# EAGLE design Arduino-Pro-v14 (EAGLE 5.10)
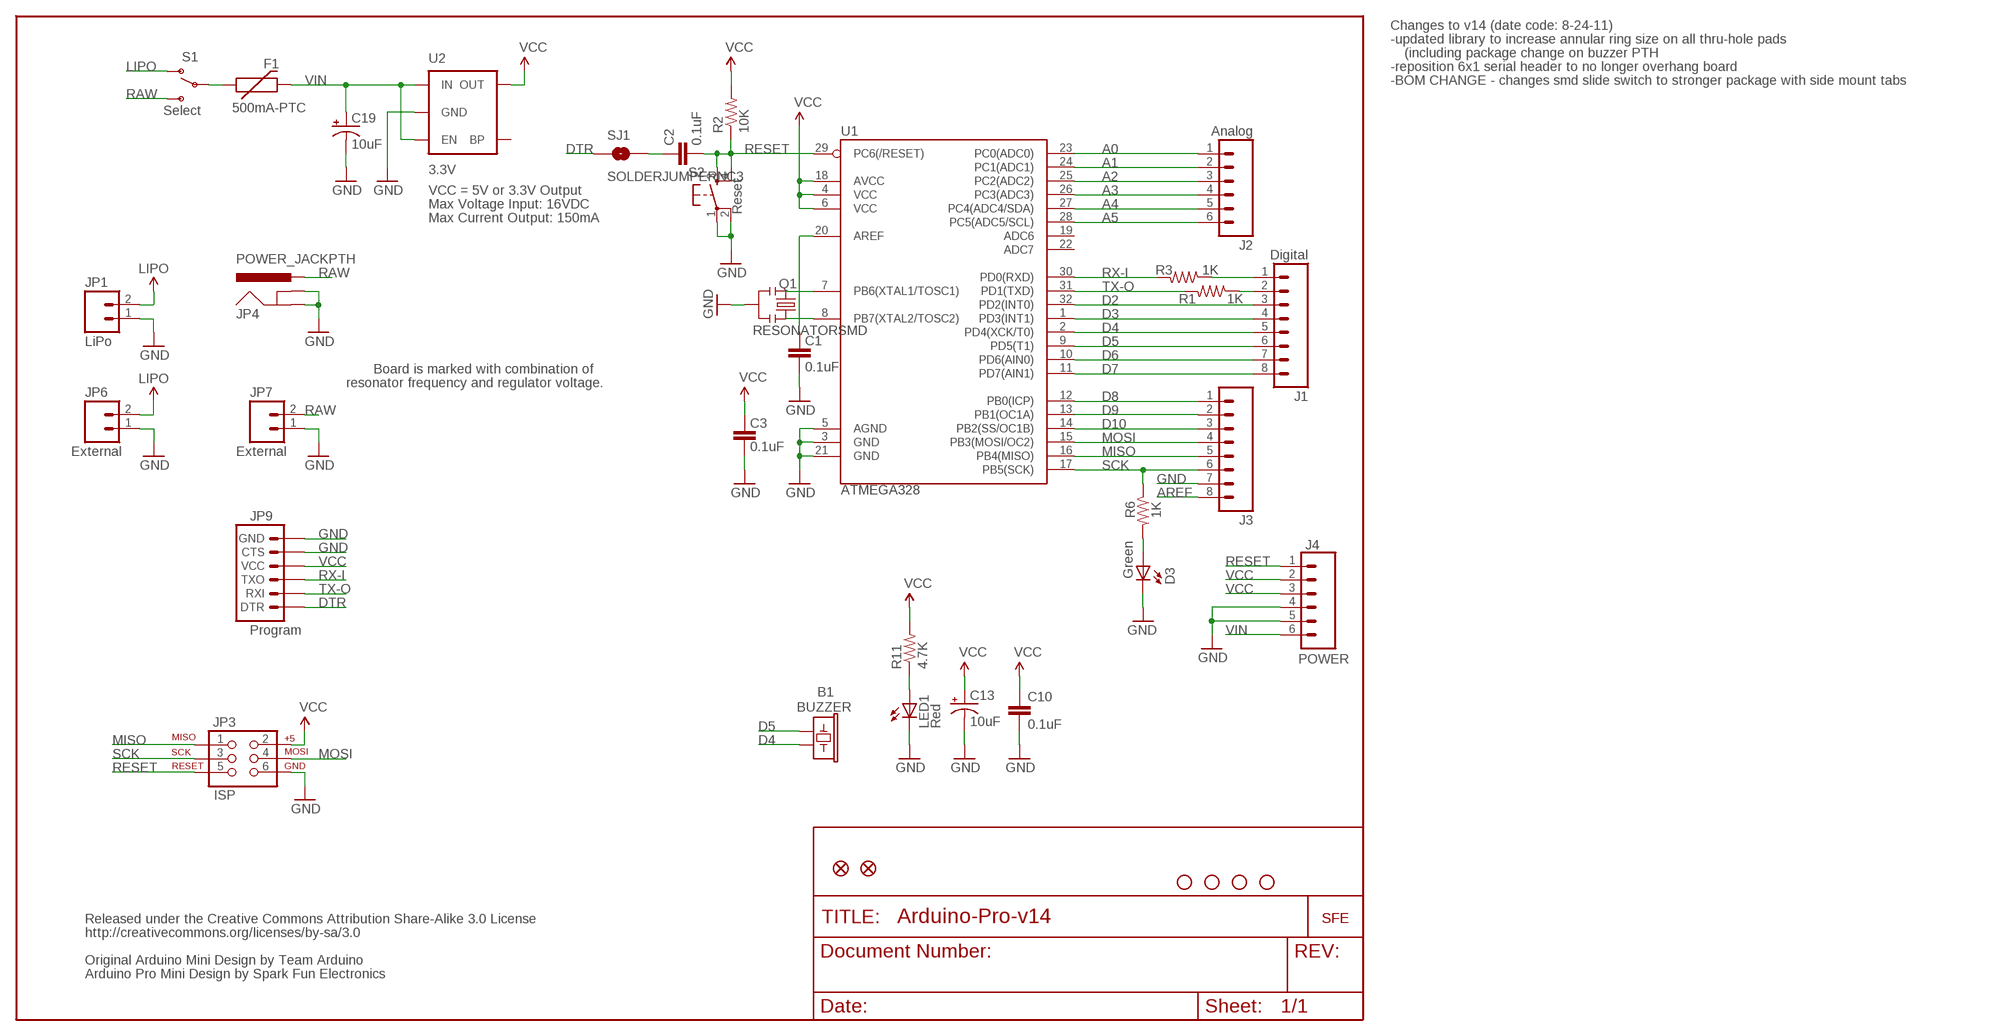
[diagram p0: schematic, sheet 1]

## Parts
B1  BUZZER  BUZZERPTH  [BUZZER-12MM]
C1  0.1uF  CAP0402-CAP  [0402-CAP]
C2  0.1uF  CAP0402-CAP  [0402-CAP]
C3  0.1uF  CAP0402-CAP  [0402-CAP]
C10  0.1uF  CAP0402-CAP  [0402-CAP]
C13  10uF  CAP_POL1206  [EIA3216]
C19  10uF  CAP_POL1206  [EIA3216]
D3  Green  LED0603  [LED-0603]
F1  500mA-PTC  PTCSMD  [PTC-1206]
J1  Digital  M081X08  [1X08]
J2  Analog  M06SIP  [1X06]
J3  M081X08  [1X08]
J4  POWER  M06SIP  [1X06]
JP1  LiPo  M02-JST-2MM-SMT  [JST-2-SMD]
JP2  FIDUCIAL1X2.5  [FIDUCIAL-1X2.5]
JP3  ISP  AVR_SPI_PRG_6PTH  [2X3]
JP4  POWER_JACKPTH  [POWER_JACK_PTH]
JP5  FIDUCIAL1X2.5  [FIDUCIAL-1X2.5]
JP6  External  M02PTH  [1X02]
JP7  External  M02PTH  [1X02]
JP9  Program  ARDUINO_SERIAL_PROGRAMSMD  [1X06-SMD]
LED1  Red  LED0603  [LED-0603]
Q1  RESONATORSMD  [RESONATOR-SMD]
R1  1K  RESISTOR0402-RES  [0402-RES]
R2  10K  RESISTOR0402-RES  [0402-RES]
R3  1K  RESISTOR0402-RES  [0402-RES]
R6  1K  RESISTOR0402-RES  [0402-RES]
R11  4.7K  RESISTOR0402-RES  [0402-RES]
S1  Select  SWITCH-SPST-SMD-A  [SWITCH-SPST-SMD-A]
S2  Reset  TAC_SWITCHSMD  [TACTILE_SWITCH_SMD]
SJ1  SOLDERJUMPERNC3  SOLDERJUMPERNC2  [SJ_2S-NOTRACE]
U1  ATMEGA328  ATMEGA168  [TQFP32-08]
U2  3.3V  V_REG_LDOSMD  [SOT23-5]
U$1  STAND-OFF  [STAND-OFF]
U$3  STAND-OFF  [STAND-OFF]
U$9  STAND-OFF  [STAND-OFF]
U$10  STAND-OFF  [STAND-OFF]
U$11  LOGO-SFENEW  [SFE-NEW-WEBLOGO]

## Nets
A0: J2.1 U1.23(PC0(ADC0))
A1: J2.2 U1.24(PC1(ADC1))
A2: J2.3 U1.25(PC2(ADC2))
A3: J2.4 U1.26(PC3(ADC3))
A4: J2.5 U1.27(PC4(ADC4/SDA))
A5: J2.6 U1.28(PC5(ADC5/SCL))
AREF: C1.2 J3.8 U1.20(AREF)
D2: J1.3 U1.32(PD2(INT0))
D3: J1.4 U1.1(PD3(INT1))
D4: B1.- J1.5 U1.2(PD4(XCK/T0))
D5: B1.+ J1.6 U1.9(PD5(T1))
D6: J1.7 U1.10(PD6(AIN0))
D7: J1.8 U1.11(PD7(AIN1))
D8: J3.1 U1.12(PB0(ICP))
D9: J3.2 U1.13(PB1(OC1A))
D10: J3.3 U1.14(PB2(SS/OC1B))
DTR: JP9.1(DTR) SJ1.1
GND [vcc]: C1.1 C3.1 C10.2 C13.C(-) C19.C(-) D3.C J3.7 J4.4 J4.5 JP1.1 JP3.6 JP4.GND JP4.GNDBREAK JP6.1 JP7.1 JP9.5(CTS) JP9.6(GND) LED1.C Q1.2 S2.1 S2.2 U1.3(GND) U1.5(AGND) U1.21(GND) U2.2(GND)
LIPO: JP1.2 JP6.2 S1.1(O)
MISO: J3.5 JP3.1 U1.16(PB4(MISO))
MOSI: J3.4 JP3.4 U1.15(PB3(MOSI/OC2))
N$1: C2.1 SJ1.2
N$3: Q1.1 U1.8(PB7(XTAL2/TOSC2))
N$4: Q1.3 U1.7(PB6(XTAL1/TOSC1))
N$7: D3.A R6.2
N$25: F1.1 S1.2(P)
N$38: LED1.A R11.1
RAW [vcc]: JP4.PWR JP7.2 S1.3(S)
RESET: C2.2 J4.1 JP3.5 R2.1 S2.3 S2.4 U1.29(PC6(/RESET))
RX-I: JP9.3(TXO) R3.2 U1.30(PD0(RXD))
RX-IP: J1.2 R1.1
SCK: J3.6 JP3.3 R6.1 U1.17(PB5(SCK))
TX-O: JP9.2(RXI) R1.2 U1.31(PD1(TXD))
TX-OP: J1.1 R3.1
VCC: C3.2 C10.1 C13.A(+) J4.2 J4.3 JP3.2 JP9.4(VCC) R2.2 R11.2 U1.4(VCC) U1.6(VCC) U1.18(AVCC) U2.5(OUT)
VIN [vcc]: C19.A(+) F1.2 J4.6 U2.1(IN) U2.3(EN)
Unconnected: U1.19(ADC6) U1.22(ADC7) U2.4(BP)

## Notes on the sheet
- Changes to v14 (date code: 8-24-11)
- -updated library to increase annular ring size on all thru-hole pads
- (including package change on buzzer PTH
- -reposition 6x1 serial header to no longer overhang board
- -BOM CHANGE - changes smd slide switch to stronger package with side mount tabs
- VCC = 5V or 3.3V Output
- Max Voltage Input: 16VDC
- Max Current Output: 150mA
- Board is marked with combination of
- resonator frequency and regulator voltage.
- Released under the Creative Commons Attribution Share-Alike 3.0 License
- http://creativecommons.org/licenses/by-sa/3.0
- Original Arduino Mini Design by Team Arduino
- Arduino Pro Mini Design by Spark Fun Electronics

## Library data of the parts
B1 = SparkFun:BUZZER: Buzzer 12mm
C1-C3 C10 = SparkFun:CAP: Capacitor
C13 C19 = SparkFun:CAP_POL: Capacitor Polarized
D3 LED1 = SparkFun:LED: LEDs
F1 = SparkFun:PTC: Resettable Fuse PTC
J1 J3 = SparkFun:M08: Header 8 Standard 8-pin 0.1" header. Use with straight break away headers (SKU : PRT-00116), right angle break away headers (PRT-00553), swiss pins (PRT-00743), machine pins (PRT-00117), and female headers (PRT-00115).
J2 J4 = SparkFun:M06: Header 6 Standard 6-pin 0.1" header. Use with straight break away headers (SKU : PRT-00116), right angle break away headers (PRT-00553), swiss pins (PRT-00743), machine pins (PRT-00117), and female headers (PRT-00115). Molex polarized connector foot print use with SKU : PRT-08094 with associated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
JP1 JP6 JP7 = SparkFun:M02: Header 2
JP2 JP5 = abes:FIDUCIAL: Fiducial Alignment Points
JP3 = SparkFun:AVR_SPI_PRG_6: AVR ISP 6 Pin This is the reduced ISP connector for AVR programming. Common on Arduino. This footprint will take up less PCB space and can be used with a 10-pin to 6-pin adapter such as SKU: BOB-08508
JP4 = SparkFun:POWER_JACK: Power Jack This is the standard 5.5mm barrel jack for power. The PTH is the most common, proven, reliable, footprint. All others are experimental. The Slot footprint only works if the mill layer is transmitted to the PCB fab house so be warned. Spark Fun Electronics SKU : PRT-00119. Mating wall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
JP9 = SparkFun:ARDUINO_SERIAL_PROGRAM
Q1 = SparkFun:RESONATOR: Resonator Small SMD resonator. This is the itty bitty 10/20MHz resonators with built in caps. CSTCE10M0G55 and CSTCE20M0V53. Footprint has been reviewed closely but hasn't been tested yet.
R1-R3 R6 R11 = SparkFun:RESISTOR: Resistor
S1 = SparkFun:SWITCH-SPST: SPST Switch Simple slide switch. Spark Fun Electronics SKU : COM-00102
S2 = SparkFun:TAC_SWITCH: Momentary Switch Button commonly used for reset or general input. Spark Fun Electronics SKU : COM-00097
SJ1 = SparkFun:SOLDERJUMPER: Solder Jumper
U1 = SparkFun:ATMEGA168
U2 = SparkFun:V_REG_LDO: Voltage Regulator LDO Standard 150mA LDO voltage regulator in SOT-23 layout. Micrel part MIC5205. BP (by-pass) pin is used to lower output noise with 470pF cap.
U$1 U$3 U$9 U$10 = SparkFun:STAND-OFF: Stand Off
U$11 = SparkFun:LOGO-SFE: Spark Fun Electronics PCB Logo

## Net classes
0 default: width 0.203 mm
1 vcc: width 0.254 mm

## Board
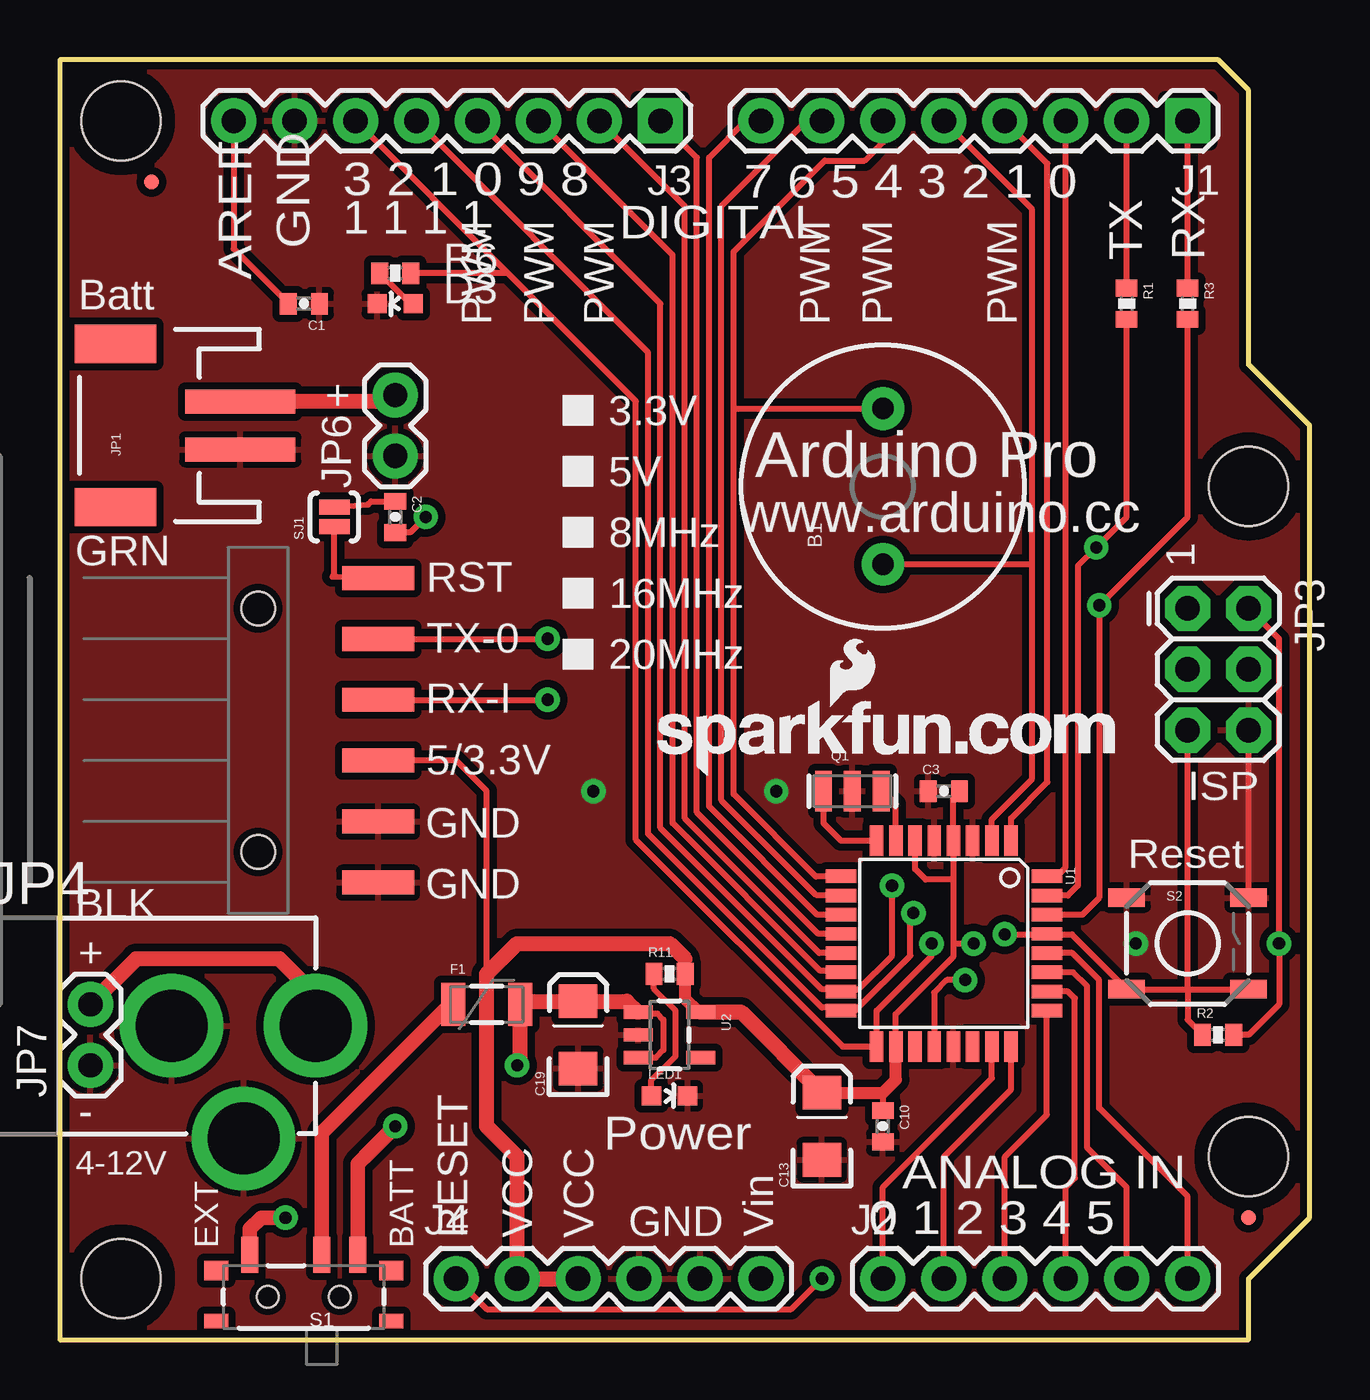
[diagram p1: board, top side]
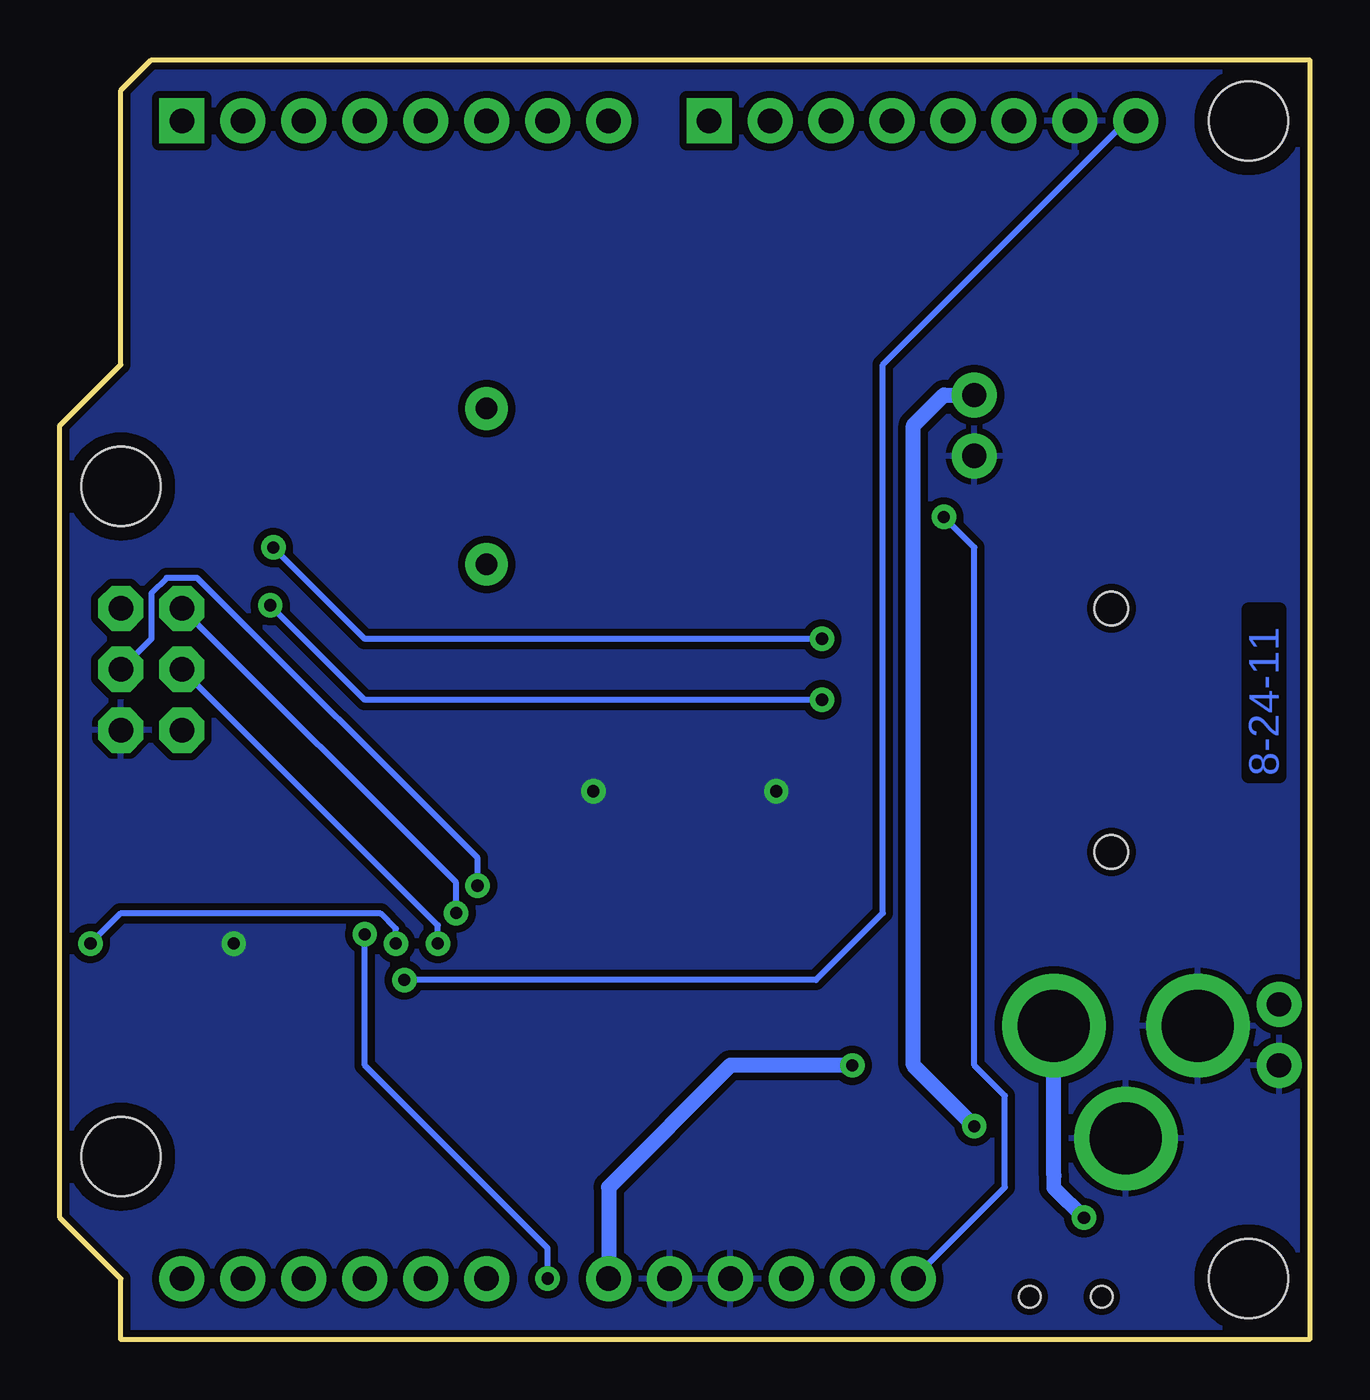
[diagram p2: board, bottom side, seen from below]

Size 52.07 x 53.34 mm. Coordinates in mm from the lower left corner, seen from the top.
Outline: 0,53.34 0,0 49.53,0 49.53,2.54 52.07,5.08 52.07,38.1 49.53,40.64 49.53,52.07 48.26,53.34 0,53.34
Copper layers (1*16): Top 0.035mm / dielectric 1.5mm / Bottom 0.035mm
Design rules "SparkFun": minimum track width 8mil, minimum drill 20mil, track to track 8mil, track to pad 8mil, pad to pad 8mil, via to via 8mil, smd to smd 8mil, copper to edge 10mil, drill to drill 8mil, minimum pad ring 12mil, minimum via ring 10mil, stop-mask expansion 4mil, vias tented up to drill 20mil, thermal gap 10mil

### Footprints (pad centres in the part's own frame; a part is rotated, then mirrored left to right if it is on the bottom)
BUZZER-12MM = drill 0.9 pad 1.778 round: + 3.25,0; - -3.25,0
0402-CAP = smd 0.7 x 0.9: 1 -0.65,0; 2 0.65,0
EIA3216 = smd 1.4 x 1.6: A 1.4,0; C -1.4,0
LED-0603 = smd 0.8 x 0.8: A 0,-0.75; C 0,0.75
PTC-1206 = smd 1 x 1.8: 1 -1.4,0; 2 1.4,0
1X08 = drill 1.016 pad 1.88 square: 1 0,0 | drill 1.016 pad 1.88 round: 2 2.54,0; 3 5.08,0; 4 7.62,0; 5 10.16,0; 6 12.7,0; 7 15.24,0; 8 17.78,0
1X06 = drill 1.016 pad 1.88 round: 1 0,0; 2 2.54,0; 3 5.08,0; 4 7.62,0; 5 10.16,0; 6 12.7,0
JST-2-SMD = smd 1 x 4.6: 1 -1,-3.7; 2 1,-3.7 | smd 1.6 x 3.4: NC1 -3.4,1.5; NC2 3.4,1.5
FIDUCIAL-1X2.5 = smd 0.635 x 0.635: 1 0,0
2X3 = drill 1.016 pad 1.88 octagon: 1 0,0; 2 0,2.54; 3 2.54,0; 4 2.54,2.54; 5 5.08,0; 6 5.08,2.54
POWER_JACK_PTH = drill 2.997 pad 4.318 round: GND 0,7.7; GNDBREAK 4.7,10.7; PWR 0,13.7
1X02 = drill 1.016 pad 1.88 round: 1 0,0; 2 2.54,0
1X06-SMD = smd 1 x 3: 1 -6.35,5; 2 -3.81,5; 3 -1.27,5; 4 1.27,5; 5 3.81,5; 6 6.35,5 | hole 1.4: -5.08,0; 5.08,0
RESONATOR-SMD = smd 0.7 x 1.7: 1 -1.2,0; 2 0,0; 3 1.2,0
0402-RES = smd 0.7 x 0.9: 1 -0.65,0; 2 0.65,0
SWITCH-SPST-SMD-A = smd 0.7 x 1.5: 1 -2.25,-1.75; 2 -0.75,-1.75; 3 2.25,-1.75 | smd 1 x 0.6: GND1 -3.65,1; GND3 3.65,1 | smd 1 x 0.8: GND2 -3.65,-1.1; GND4 3.65,-1.1 | hole 0.9: -1.5,0; 1.5,0
TACTILE_SWITCH_SMD = smd 1.524 x 0.762: 1 -2.54,1.905; 2 2.54,1.905; 3 -2.54,-1.905; 4 2.54,-1.905
SJ_2S-NOTRACE = smd 0.635 x 1.27: 1 -0.401,0; 2 0.413,0
TQFP32-08 = smd 1.27 x 0.559: 1 -4.293,2.8; 2 -4.293,2; 3 -4.293,1.2; 4 -4.293,0.4; 5 -4.293,-0.4; 6 -4.293,-1.2; 7 -4.293,-2; 8 -4.293,-2.8; 17 4.293,-2.8; 18 4.293,-2; 19 4.293,-1.2; 20 4.293,-0.4; 21 4.293,0.4; 22 4.293,1.2; 23 4.293,2; 24 4.293,2.8 | smd 0.559 x 1.27: 9 -2.8,-4.293; 10 -2,-4.293; 11 -1.2,-4.293; 12 -0.4,-4.293; 13 0.4,-4.293; 14 1.2,-4.293; 15 2,-4.293; 16 2.8,-4.293; 25 2.8,4.293; 26 2,4.293; 27 1.2,4.293; 28 0.4,4.293; 29 -0.4,4.293; 30 -1.2,4.293; 31 -2,4.293; 32 -2.8,4.293
SOT23-5 = smd 0.55 x 1.2: 1 -0.95,-1.3; 2 0,-1.3; 3 0.95,-1.3; 4 0.95,1.3; 5 -0.95,1.3
STAND-OFF = hole 3.302: 0,0

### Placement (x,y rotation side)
B1  34.29,35.56 90 top
C1  10.16,43.18 180 top
C2  13.97,34.29 270 top
C3  36.83,22.86 0 top
C10  34.29,8.89 270 top
C13  31.75,8.89 90 top
C19  21.59,12.7 90 top
D3  13.97,43.18 90 top
F1  17.78,13.97 0 top
J1  46.99,50.8 180 top
J2  34.29,2.54 0 top
J3  25.02,50.8 180 top
J4  16.51,2.54 0 top
JP1  3.81,38.1 90 top
JP2  49.53,5.08 0 top
JP3  46.99,30.48 270 top
JP4  -3.05,13.08 270 top
JP5  3.81,48.26 0 top
JP6  13.97,36.83 90 top
JP7  1.27,11.43 90 top
JP9  8.26,25.4 270 top
LED1  25.4,10.16 270 top
Q1  33.02,22.86 0 top
R1  44.45,43.18 270 top
R2  48.26,12.7 0 top
R3  46.99,43.18 270 top
R6  13.97,44.45 180 top
R11  25.4,15.24 0 top
S1  10.16,1.78 180 top
S2  46.99,16.51 0 top
SJ1  11.43,34.29 90 top
U1  36.83,16.51 270 top
U2  25.4,12.7 270 top
U$1  2.54,50.8 0 top
U$3  2.54,2.54 0 top
U$9  49.53,35.56 0 top
U$10  49.53,7.62 0 top
U$11  24.89,23.5 0 top

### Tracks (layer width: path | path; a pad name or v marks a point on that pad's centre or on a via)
A0
  Top 0.254: U1.23 38.83,10.89 34.29,6.35 J2.1
A1
  Top 0.254: U1.24 39.63,10.42 36.83,7.62 J2.2
A2
  Top 0.254: U1.25 41.12,9.37 39.37,7.62 39.37,2.79 39.5,2.67 J2.3
A3
  Top 0.254: U1.26 42.01,14.51 42.29,14.22 42.29,6.73 41.91,6.35 J2.4
A4
  Top 0.254: U1.27 42.22,15.31 42.8,14.73 42.8,8 44.45,6.35 J2.5
A5
  Top 0.254: U1.28 42.18,16.11 43.31,14.99 43.31,9.65 46.99,5.97 J2.6
AREF  (via drill 0.51)
  Top 0.254: U1.20 36.43,14.46 36.96,14.99 v37.72,14.99 | C1.2 9.53,43.18 7.24,45.47 J3.8
  Bottom 0.254: v37.72,14.99 20.57,14.99 17.78,17.78 17.78,40.64 7.62,50.8 J3.8
D2
  Top 0.254: U1.32 41.52,19.31 41.53,19.3 41.91,19.68 J1.3
D3
  Top 0.254: U1.1 39.63,21.72 41.15,23.24 41.15,49.02 J1.4
D4
  Top 0.254: U1.2 38.83,21.68 40.51,23.37 40.51,32.26 | 40.51,32.26 40.51,47.12 J1.5 | B1.- 40.46,32.31 40.51,32.26
D5
  Top 0.254: U1.9 32.64,19.3 | U1.9 | U1.9 31.5,19.3 28.07,22.73 28.07,38.86 | 28.07,38.86 28.07,45.34 31.88,49.15 33.53,49.15 34.29,49.91 J1.6 | B1.+ 28.12,38.81 28.07,38.86
D6
  Top 0.254: U1.10 32.42,18.51 32.38,18.54 31.5,18.54 27.56,22.48 27.56,47.24 31.11,50.8 J1.7
D7
  Top 0.254: U1.11 31.57,17.71 27.05,22.23 27.05,49.28 28.57,50.8 J1.8
D8
  Top 0.254: U1.12 31.6,16.91 26.54,21.97 26.54,49.28 J3.1
D9
  Top 0.254: U1.13 31.64,16.11 26.04,21.72 26.04,47.24 J3.2
D10
  Top 0.254: J3.3 25.53,45.21 25.53,21.53 31.69,15.37 32.51,15.37 32.51,15.34 U1.14
DTR
  Top 0.254: JP9.1 11.35,31.8 11.43,31.88 SJ1.1
GND  (via drill 0.51)
  Top 0.254: S2.2 JP3.6
  other vias: 29.84,22.86 22.23,22.86 44.83,16.51
  pour Top (isolate 0.305): 0,53.34 52.07,53.34 52.07,0 0,0
  pour Bottom (isolate 0.305): 0,53.34 52.07,53.34 52.07,0 0,0
LIPO  (via drill 0.51)
  Top 0.61: 12.7,7.62 12.41,7.33 S1.1
  Top 0.635: JP1.2 13.7,39.1 JP6.2 | 12.7,7.62 v13.97,8.89
  Bottom 0.635: JP6.2 15.24,39.37 16.51,38.1 16.51,11.43 v13.97,8.89
MISO  (via drill 0.51)
  Top 0.254: J3.5 24.51,41.15 24.51,21.08 31.75,13.84 32.64,13.84 32.54,13.74 U1.16 | U1.16 | U1.16 32.63,13.71 32.64,13.72 33.15,13.72 35.43,16 35.43,17.65 v35.56,17.78
  Bottom 0.254: JP3.1 35.56,19.05 v35.56,17.78
MOSI  (via drill 0.51)
  Top 0.254: J3.4 25.02,43.18 25.02,21.34 31.75,14.61 32.51,14.61 32.54,14.58 U1.15 | 32.64,14.48 32.57,14.48 U1.15 | v34.67,18.92 34.67,16 33.27,14.61 32.77,14.61 32.64,14.48 | 32.64,14.48 32.61,14.51 U1.15
  Bottom 0.254: JP3.4 48.26,29.21 48.26,31.11 47.62,31.75 46.35,31.75 34.67,20.07 v34.67,18.92
N$1
  Top 0.254: C2.1 12.97,34.94 12.83,34.8 SJ1.2
N$3
  Top 0.254: U1.8 32.54,20.8 31.82,21.52 Q1.1
N$4
  Top 0.254: Q1.3 34.29,22.86 34.83,22.32 U1.7
N$7
  Top 0.254: D3.A 14.61,43.18 13.34,44.45 R6.2
N$25
  Top 0.61: F1.1 16.26,13.97 10.91,8.62 S1.2
  Top 0.635: F1.1 16.51,13.97
N$38
  Top 0.254: R11.1 24.75,14.62 25.65,13.72 25.65,11.81 24.64,10.79 24.64,10.16 LED1.A
RAW  (via drill 0.51)
  Top 0.61: v9.4,5.08 8.38,5.08 7.91,4.61 S1.3
  Top 0.635: JP7.2 3.17,15.88 9.14,15.88 10.67,14.35 10.67,12.7 JP4.PWR
  Bottom 0.61: 10.65,6.84 10.65,6.33 v9.4,5.08
  Bottom 0.635: 10.65,6.84 JP4.PWR
RESET  (via drill 0.51)
  Top 0.254: S2.4 49.66,14.61 | J4.1 17.78,1.27 30.48,1.27 v31.75,2.54 | v39.37,16.89 41.02,16.89 41.04,16.91 U1.29 41.26,16.91 41.27,16.89 42.16,16.89 S2.3 46.99,14.61 | S2.4 49.4,14.61 | 46.99,14.61 JP3.5 | R2.1 47.62,12.7 46.99,13.34 46.99,14.61 | 46.99,14.61 S2.4 | C2.2 14.59,33.64 v15.24,34.29
  Bottom 0.254: v39.37,16.89 39.37,11.43 31.75,3.81 v31.75,2.54 | J4.1 12.7,6.35 12.7,10.16 13.97,11.43 13.97,33.02 v15.24,34.29
RX-I  (via drill 0.51)
  Top 0.254: U1.30 42.6,17.71 43.31,18.41 v43.31,30.61 46.99,34.29 R3.2 | JP9.3 v20.32,26.67
  Bottom 0.254: v20.32,26.67 39.37,26.67 v43.31,30.61
RX-IP
  Top 0.254: R1.1 J1.2
SCK  (via drill 0.51)
  Top 0.254: 18.67,44.45 24,39.12 24,20.83 32.61,12.22 U1.17 34.03,13.71 36.32,16 v36.32,16.51 | 18.67,44.45 J3.6 | 14.62,44.47 R6.1 18.67,44.45
  Bottom 0.254: v36.32,16.51 36.32,17.27 JP3.3
TX-O  (via drill 0.51)
  Top 0.254: U1.31 42.01,18.51 42.42,18.92 42.42,32.26 v43.18,33.02 44.45,34.29 R1.2 | JP9.2 v20.32,29.21
  Bottom 0.254: v20.32,29.21 39.37,29.21 v43.18,33.02
TX-OP
  Top 0.254: R3.1 J1.1
VCC  (via drill 0.51)
  Top 0.254: 34.29,10.29 C10.1 | C13.A 31.75,10.16 | 26.54,13.59 26.6,13.65 26.61,13.65 U2.5 | U1.18 34.82,13.56 37.24,15.98 37.24,16.51 | U1.4 37.24,20.9 | U1.4 37.23,22.57 37.52,22.86 C3.2 | 37.24,16.51 37.24,19.18 | 37.24,19.18 U1.4 | JP3.2 50.8,29.21 v50.8,16.51 50.8,13.97 49.53,12.7 R2.2 | 37.24,16.51 v38.08,16.51 | 17.78,15.24 17.78,22.86 16.51,24.13 JP9.4 | U1.6 35.63,19.61 36.07,19.18 37.24,19.18
  Top 0.508: U1.18 34.83,10.83 34.29,10.29 31.88,10.29 | 26.05,15.86 R11.2 26.04,15.24 26.04,14.22 26.61,13.65
  Top 0.635: U2.5 28.39,13.65 C13.A 31.87,10.29 31.88,10.29 | 26.05,15.86 25.4,16.51 19.05,16.51 17.78,15.24 17.78,8.89 19.05,7.62 J4.2 J4.3
  Bottom 0.254: v38.08,16.51 38.08,17.12 38.71,17.75 49.55,17.75 v50.8,16.51
VIN  (via drill 0.51)
  Top 0.254: U2.3 24.83,11.75 25.15,12.06 25.15,13.34 24.89,13.59 24.13,13.59 24.1,13.62 U2.1
  Top 0.635: U2.1 24.07,13.65 23.62,14.1 C19.A 19.18,14.1 19.05,13.97 F1.2 19.18,11.56 v19.05,11.43
  Bottom 0.635: J4.6 29.21,6.35 24.13,11.43 v19.05,11.43

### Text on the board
Bottom: 8-24-11
tPlace: Released under the Creative Commons Attribution Share-Alike 3.0 License | http://creativecommons.org/licenses/by-sa/3.0 | 3 2 1 0 9 8 | 7 6 5 4 3 2 1 0 | 1 1 1 1 | DIGITAL | GND | TX | RX | AREF | Batt | PWM | PWM | PWM | PWM | PWM | PWM | + | 3.3V | - | 5V | Arduino Pro | www.arduino.cc | 8MHz | GRN | 1 | RST | 16MHz | TX-0 | 20MHz | RX-I | 5/3.3V | ISP | GND | Reset | BLK | GND | + | - | Power | 4-12V | ANALOG IN | EXT | BATT | RESET | VCC | VCC | GND | Vin | 0 1 2 3 4 5
tValues: DNP | DNP | JST-Right Angle | DNP | Production: DNP | Production: DNP | Proto: 2x3 male header up | DNP | DNP | DNP | Arduino Pro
